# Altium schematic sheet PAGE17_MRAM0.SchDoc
size 381 x 381 mm; SheetNumber: 18; SheetTotal: 28
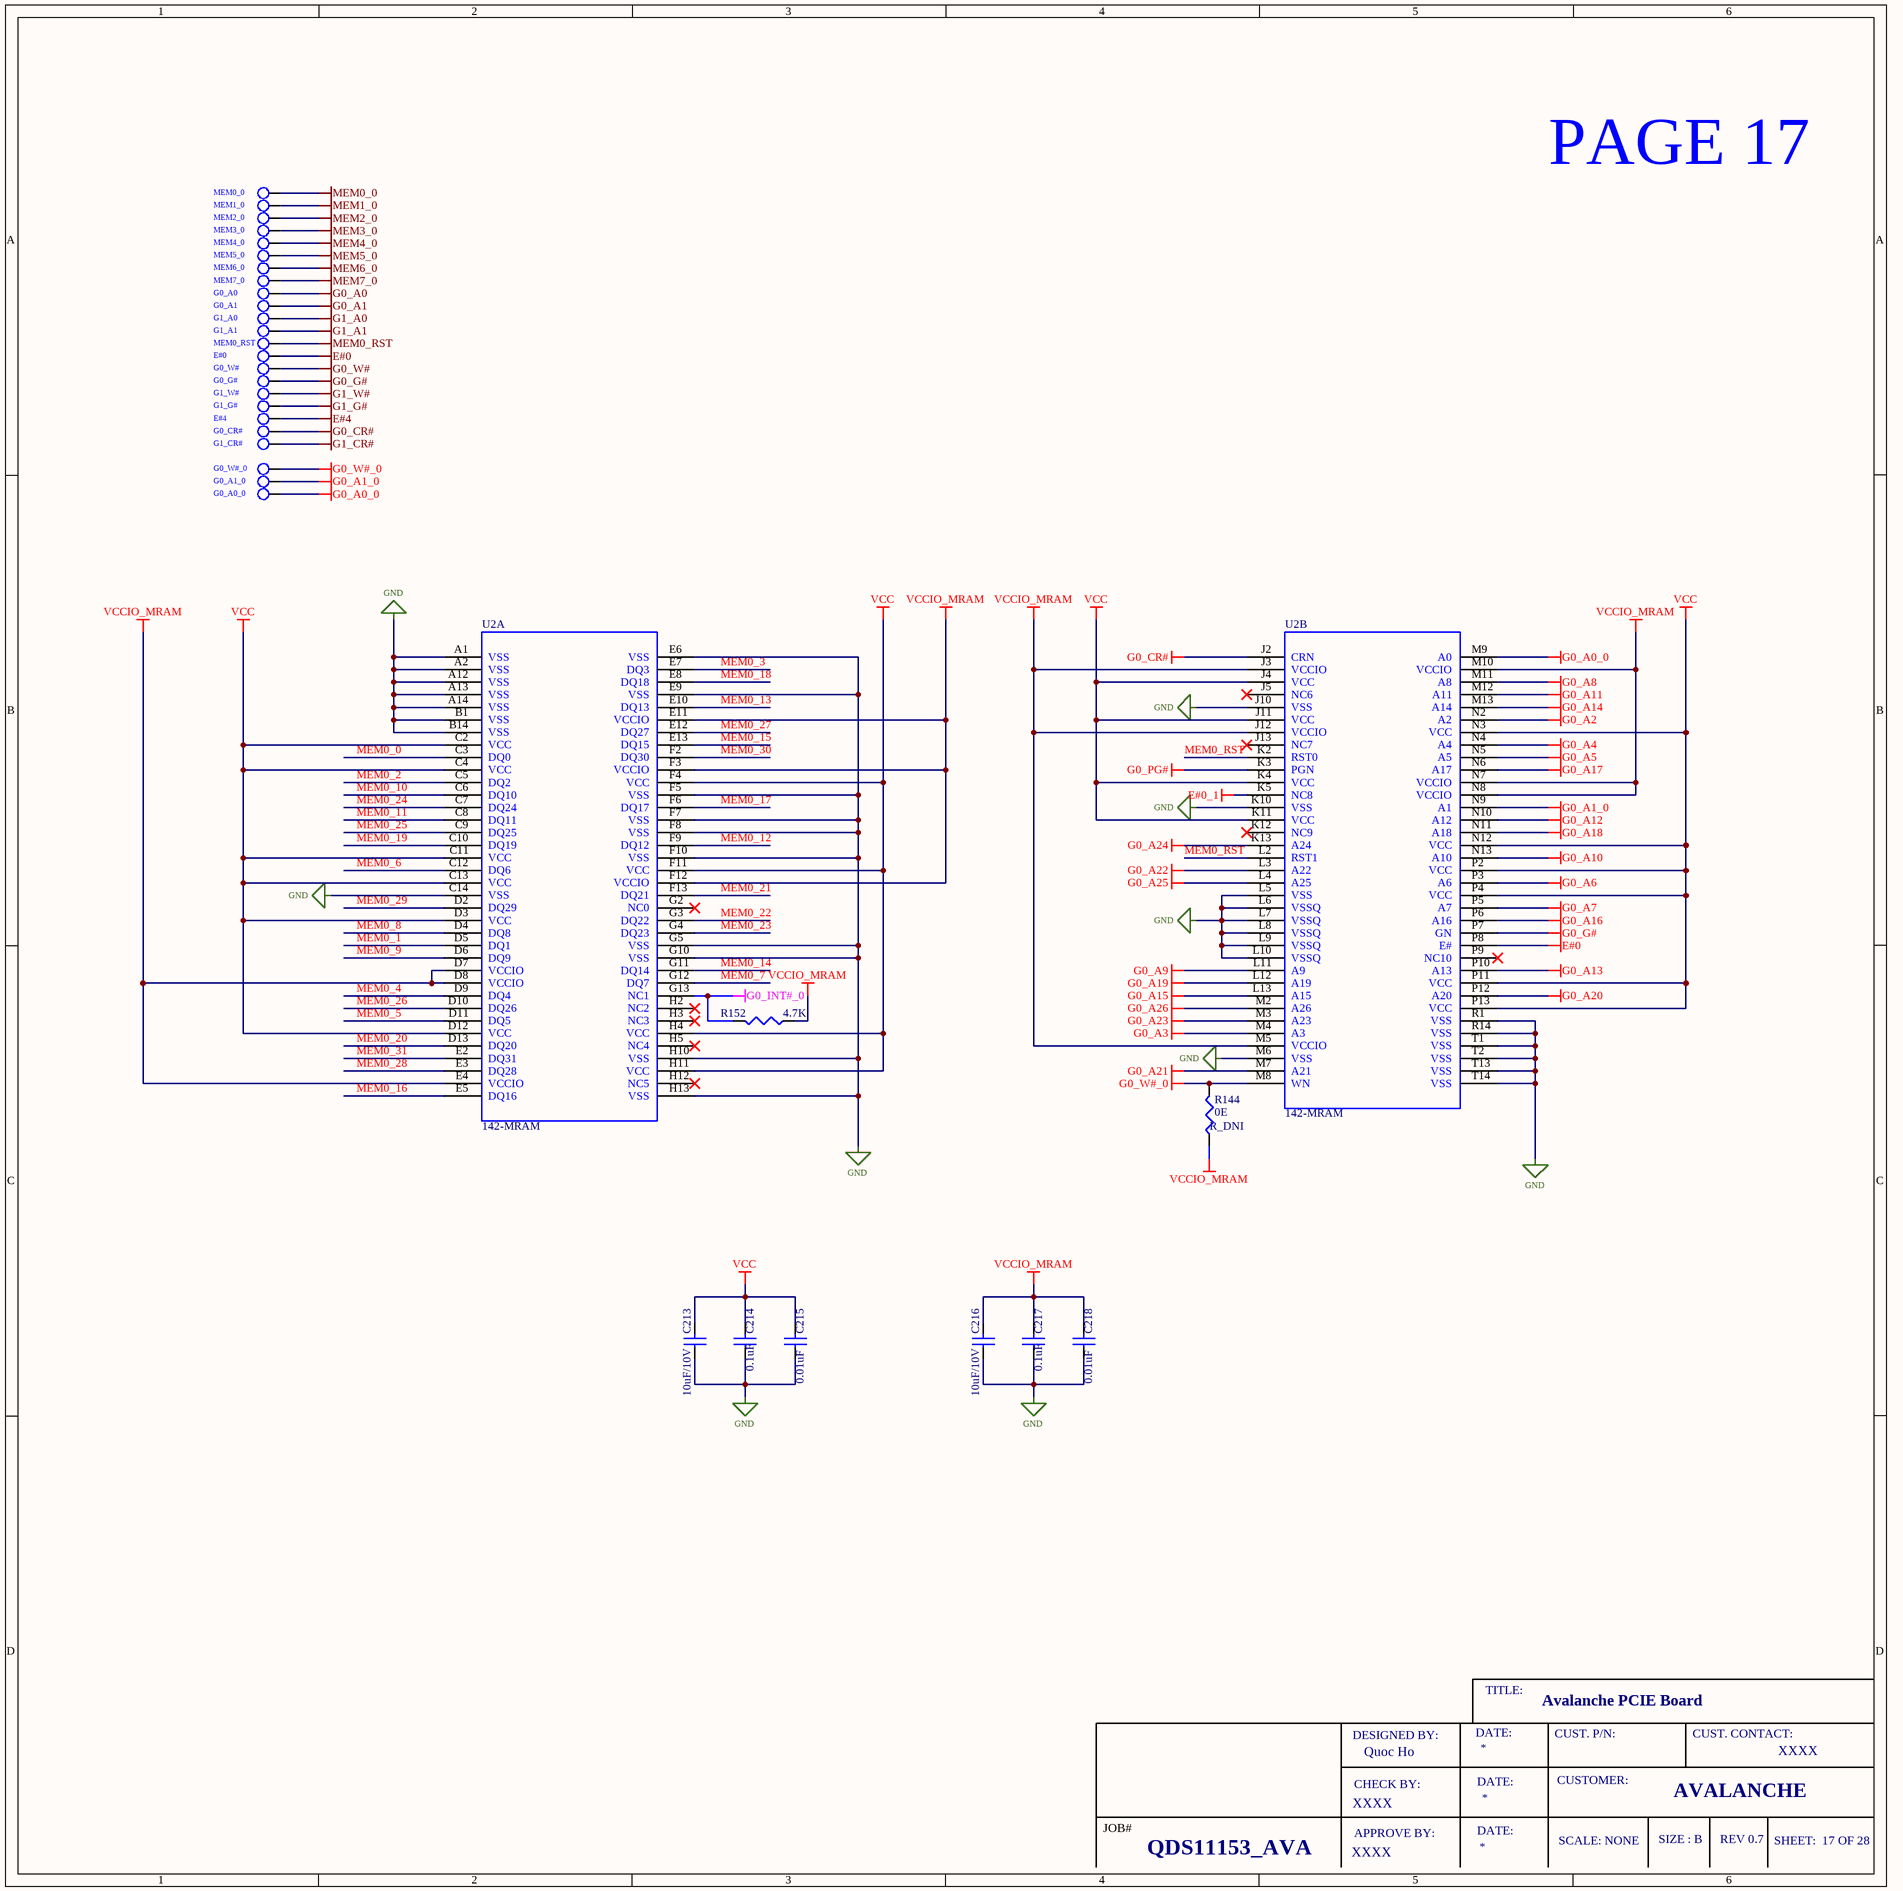
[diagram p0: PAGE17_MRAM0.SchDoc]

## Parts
C213  10uF/10V  [CN_0402]
C214  0.1uF  [CN_0402]
C215  0.01uF  [CN_0402]
C216  10uF/10V  [CN_0402]
C217  0.1uF  [CN_0402]
C218  0.01uF  [CN_0402]
E#0  TP_DNI  [MINI_TESTPOINT]  (value not drawn)
E#4  TP_DNI  [MINI_TESTPOINT]  (value not drawn)
G0_A0  TP_DNI  [MINI_TESTPOINT]  (value not drawn)
G0_A0_0  TP_DNI  [MINI_TESTPOINT]  (value not drawn)
G0_A1  TP_DNI  [MINI_TESTPOINT]  (value not drawn)
G0_A1_0  TP_DNI  [MINI_TESTPOINT]  (value not drawn)
G0_CR#  TP_DNI  [MINI_TESTPOINT]  (value not drawn)
G0_G#  TP_DNI  [MINI_TESTPOINT]  (value not drawn)
G0_W#  TP_DNI  [MINI_TESTPOINT]  (value not drawn)
G0_W#_0  TP_DNI  [MINI_TESTPOINT]  (value not drawn)
G1_A0  TP_DNI  [MINI_TESTPOINT]  (value not drawn)
G1_A1  TP_DNI  [MINI_TESTPOINT]  (value not drawn)
G1_CR#  TP_DNI  [MINI_TESTPOINT]  (value not drawn)
G1_G#  TP_DNI  [MINI_TESTPOINT]  (value not drawn)
G1_W#  TP_DNI  [MINI_TESTPOINT]  (value not drawn)
MEM0_0  TP_DNI  [MINI_TESTPOINT]  (value not drawn)
MEM0_RST  TP_DNI  [MINI_TESTPOINT]  (value not drawn)
MEM1_0  TP_DNI  [MINI_TESTPOINT]  (value not drawn)
MEM2_0  TP_DNI  [MINI_TESTPOINT]  (value not drawn)
MEM3_0  TP_DNI  [MINI_TESTPOINT]  (value not drawn)
MEM4_0  TP_DNI  [MINI_TESTPOINT]  (value not drawn)
MEM5_0  TP_DNI  [MINI_TESTPOINT]  (value not drawn)
MEM6_0  TP_DNI  [MINI_TESTPOINT]  (value not drawn)
MEM7_0  TP_DNI  [MINI_TESTPOINT]  (value not drawn)
R144  0E  [RN_0402]
R152  4.7K  [RN_0402]
U2  142-MRAM  [142-MRAM]  (parts A,B of 2)

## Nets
E#0: E#0.1 U2.P8(E#)
E#0_1: U2.K5(NC8)
E#4: E#4.1
G0_A0: G0_A0.1
G0_A0_0: G0_A0_0.1 U2.M9(A0)
G0_A1: G0_A1.1
G0_A1_0: G0_A1_0.1 U2.N9(A1)
G0_A2: U2.N2(A2)
G0_A3: U2.M4(A3)
G0_A4: U2.N4(A4)
G0_A5: U2.N5(A5)
G0_A6: U2.P3(A6)
G0_A7: U2.P5(A7)
G0_A8: U2.M11(A8)
G0_A9: U2.L11(A9)
G0_A10: U2.N13(A10)
G0_A11: U2.M12(A11)
G0_A12: U2.N10(A12)
G0_A13: U2.P10(A13)
G0_A14: U2.M13(A14)
G0_A15: U2.L13(A15)
G0_A16: U2.P6(A16)
G0_A17: U2.N6(A17)
G0_A18: U2.N11(A18)
G0_A19: U2.L12(A19)
G0_A20: U2.P12(A20)
G0_A21: U2.M7(A21)
G0_A22: U2.L3(A22)
G0_A23: U2.M3(A23)
G0_A24: U2.K13(A24)
G0_A25: U2.L4(A25)
G0_A26: U2.M2(A26)
G0_CR#: G0_CR#.1 U2.J2(CRN)
G0_G#: G0_G#.1 U2.P7(GN)
G0_INT#_0: R152.2 U2.G13(NC1)
G0_PG#: U2.K3(PGN)
G0_W#: G0_W#.1
G0_W#_0: G0_W#_0.1 R144.2 U2.M8(WN)
G1_A0: G1_A0.1
G1_A1: G1_A1.1
G1_CR#: G1_CR#.1
G1_G#: G1_G#.1
G1_W#: G1_W#.1
GND: C213.1 C214.1 C215.1 C216.1 C217.1 C218.1 U2.A1(VSS) U2.A2(VSS) U2.A12(VSS) U2.A13(VSS) U2.A14(VSS) U2.B1(VSS) U2.B14(VSS) U2.C14(VSS) U2.E6(VSS) U2.E9(VSS) U2.F5(VSS) U2.F7(VSS) U2.F8(VSS) U2.F10(VSS) U2.G5(VSS) U2.G10(VSS) U2.H10(VSS) U2.H13(VSS) U2.J10(VSS) U2.K10(VSS) U2.L5(VSS) U2.L6(VSSQ) U2.L7(VSSQ) U2.L8(VSSQ) U2.L9(VSSQ) U2.L10(VSSQ) U2.M6(VSS) U2.R1(VSS) U2.R14(VSS) U2.T1(VSS) U2.T2(VSS) U2.T13(VSS) U2.T14(VSS)
MEM0_0: MEM0_0.1 U2.C3(DQ0)
MEM0_RST: MEM0_RST.1 U2.K2(RST0) U2.L2(RST1)
MEM1_0: MEM1_0.1
MEM2_0: MEM2_0.1
MEM3_0: MEM3_0.1
MEM4_0: MEM4_0.1
MEM5_0: MEM5_0.1
MEM6_0: MEM6_0.1
MEM7_0: MEM7_0.1
VCC: C213.2 C214.2 C215.2 U2.C2(VCC) U2.C4(VCC) U2.C11(VCC) U2.C13(VCC) U2.D3(VCC) U2.D12(VCC) U2.F4(VCC) U2.F11(VCC) U2.H4(VCC) U2.H11(VCC) U2.J4(VCC) U2.J11(VCC) U2.K4(VCC) U2.K11(VCC) U2.N3(VCC) U2.N12(VCC) U2.P2(VCC) U2.P4(VCC) U2.P11(VCC) U2.P13(VCC)
VCCIO_MRAM: C216.2 C217.2 C218.2 R144.1 R152.1 U2.D7(VCCIO) U2.D8(VCCIO) U2.E4(VCCIO) U2.E11(VCCIO) U2.F3(VCCIO) U2.F12(VCCIO) U2.J3(VCCIO) U2.J12(VCCIO) U2.M5(VCCIO) U2.M10(VCCIO) U2.N7(VCCIO) U2.N8(VCCIO)
MEM0_1: U2.D5(DQ1)
MEM0_2: U2.C5(DQ2)
MEM0_3: U2.E7(DQ3)
MEM0_4: U2.D9(DQ4)
MEM0_5: U2.D11(DQ5)
MEM0_6: U2.C12(DQ6)
MEM0_7: U2.G12(DQ7)
MEM0_8: U2.D4(DQ8)
MEM0_9: U2.D6(DQ9)
MEM0_10: U2.C6(DQ10)
MEM0_11: U2.C8(DQ11)
MEM0_12: U2.F9(DQ12)
MEM0_13: U2.E10(DQ13)
MEM0_14: U2.G11(DQ14)
MEM0_15: U2.E13(DQ15)
MEM0_16: U2.E5(DQ16)
MEM0_17: U2.F6(DQ17)
MEM0_18: U2.E8(DQ18)
MEM0_19: U2.C10(DQ19)
MEM0_20: U2.D13(DQ20)
MEM0_21: U2.F13(DQ21)
MEM0_22: U2.G3(DQ22)
MEM0_23: U2.G4(DQ23)
MEM0_24: U2.C7(DQ24)
MEM0_25: U2.C9(DQ25)
MEM0_26: U2.D10(DQ26)
MEM0_27: U2.E12(DQ27)
MEM0_28: U2.E3(DQ28)
MEM0_29: U2.D2(DQ29)
MEM0_30: U2.F2(DQ30)
MEM0_31: U2.E2(DQ31)

Not connected (* = marked no-connect by the designer): U2 G2(NC0)* H2(NC2)* H3(NC3)* H5(NC4)* H12(NC5)* J5(NC6)* J13(NC7)* K12(NC9)* P9(NC10)*

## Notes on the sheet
- PAGE 17
- TITLE:
- Avalanche PCIE Board
- DESIGNED BY:
- CHECK BY:
- Quoc Ho
- DATE:
- CUST. P/N:
- CUSTOMER:
- CUST. CONTACT:
- XXXX
- JOB#
- APPROVE BY:
- SCALE: NONE
- SIZE : B
- AVALANCHE
- REV 0.7
- SHEET:  17 OF 28
- QDS11153_AVA

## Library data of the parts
C213 C216 = CAP: CAP CER 10UF 10V X5R 0402; Manufacturer Part Number: GRM155R61A106ME11D; Manufacturer: Murata Electronics
C214 C217 = CAP: CAP CER 0.1UF 50V X7R 0402; Manufacturer Part Number: GCM155R71H104KE02J; Manufacturer: Murata Electronics
C215 C218 = CAP: 0.01 µF, 25 V, 0402 [1005 Metric], ± 10%, X7R; Manufacturer: YAGEO; Manufacturer Part Number: CC0402JRX7R8BB103
E#0 E#4 G0_A0 G0_A0_0 G0_A1 G0_A1_0 G0_CR# G0_G# G0_W# G0_W#_0 G1_A0 G1_A1 G1_CR# G1_G# G1_W# MEM0_0 MEM0_RST MEM1_0 MEM2_0 MEM3_0 MEM4_0 MEM5_0 MEM6_0 MEM7_0 = TEST_POINT: Tap_point 15X25
R144 = RES: RES 0 OHM JUMPER 1/16W 0402; Manufacturer Part Number: RC0402FR-070RL; Manufacturer: YAGEO
R152 = RES: RES 4.7K OHM 1% 1/16W 0402; Manufacturer Part Number: RC0402FR-134K7L; Manufacturer: YAGEO
U2 = 142-MRAM: IC 142-MRAM MEMORY; Manufacturer: Avalanche Technology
